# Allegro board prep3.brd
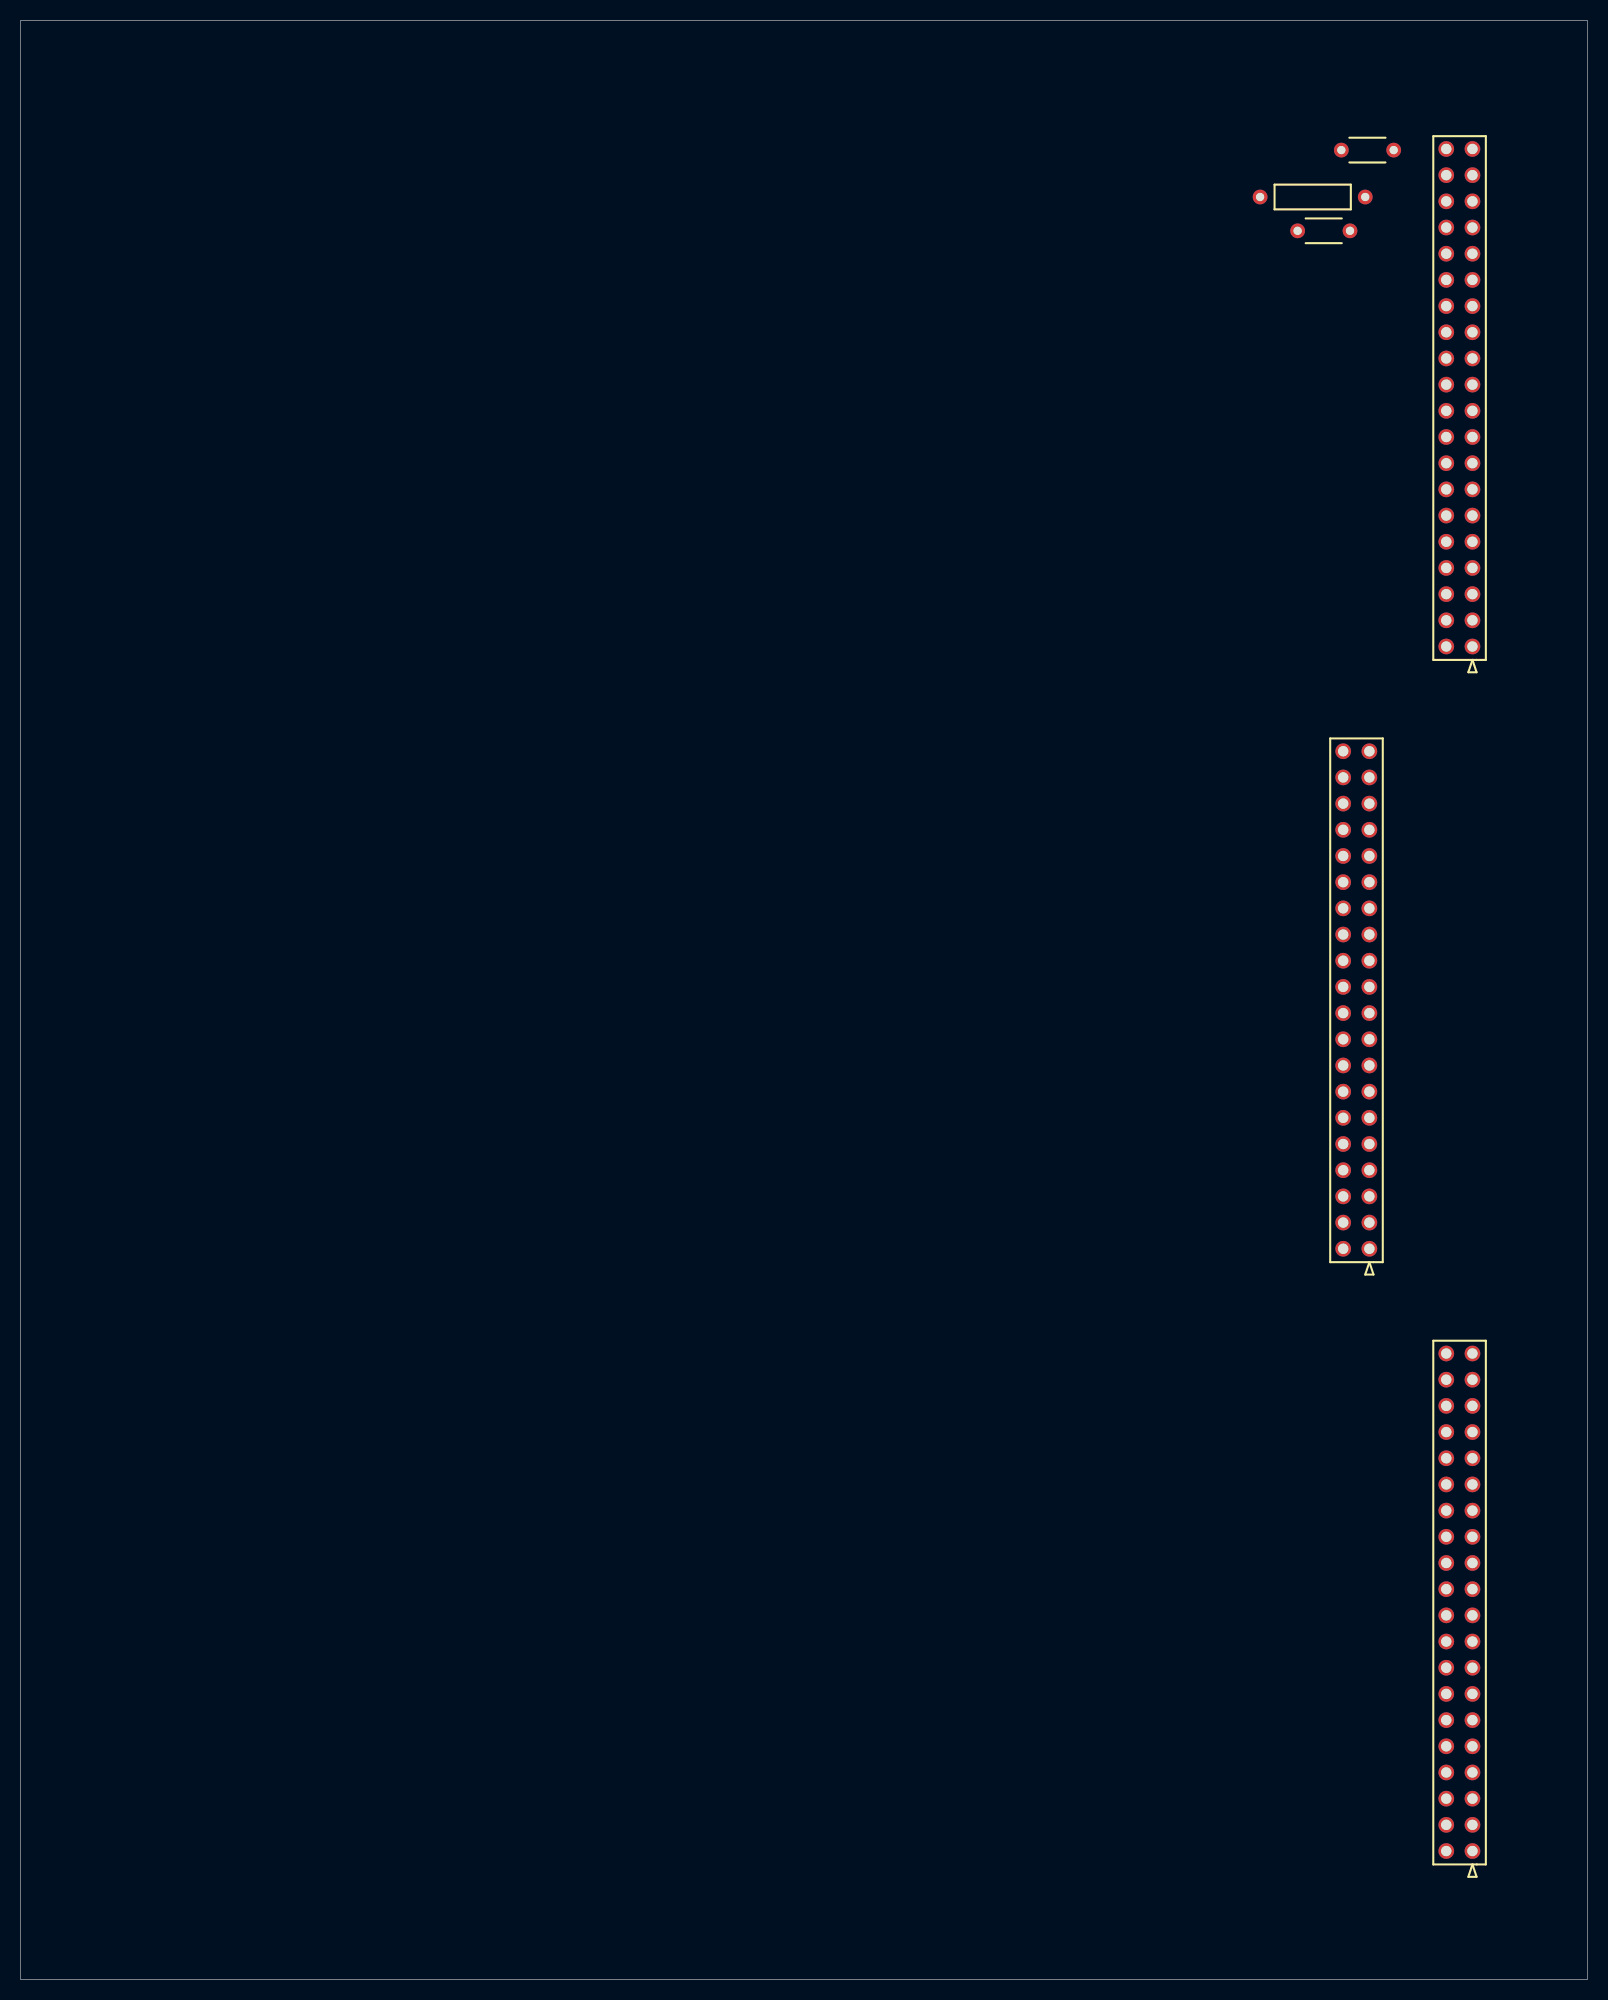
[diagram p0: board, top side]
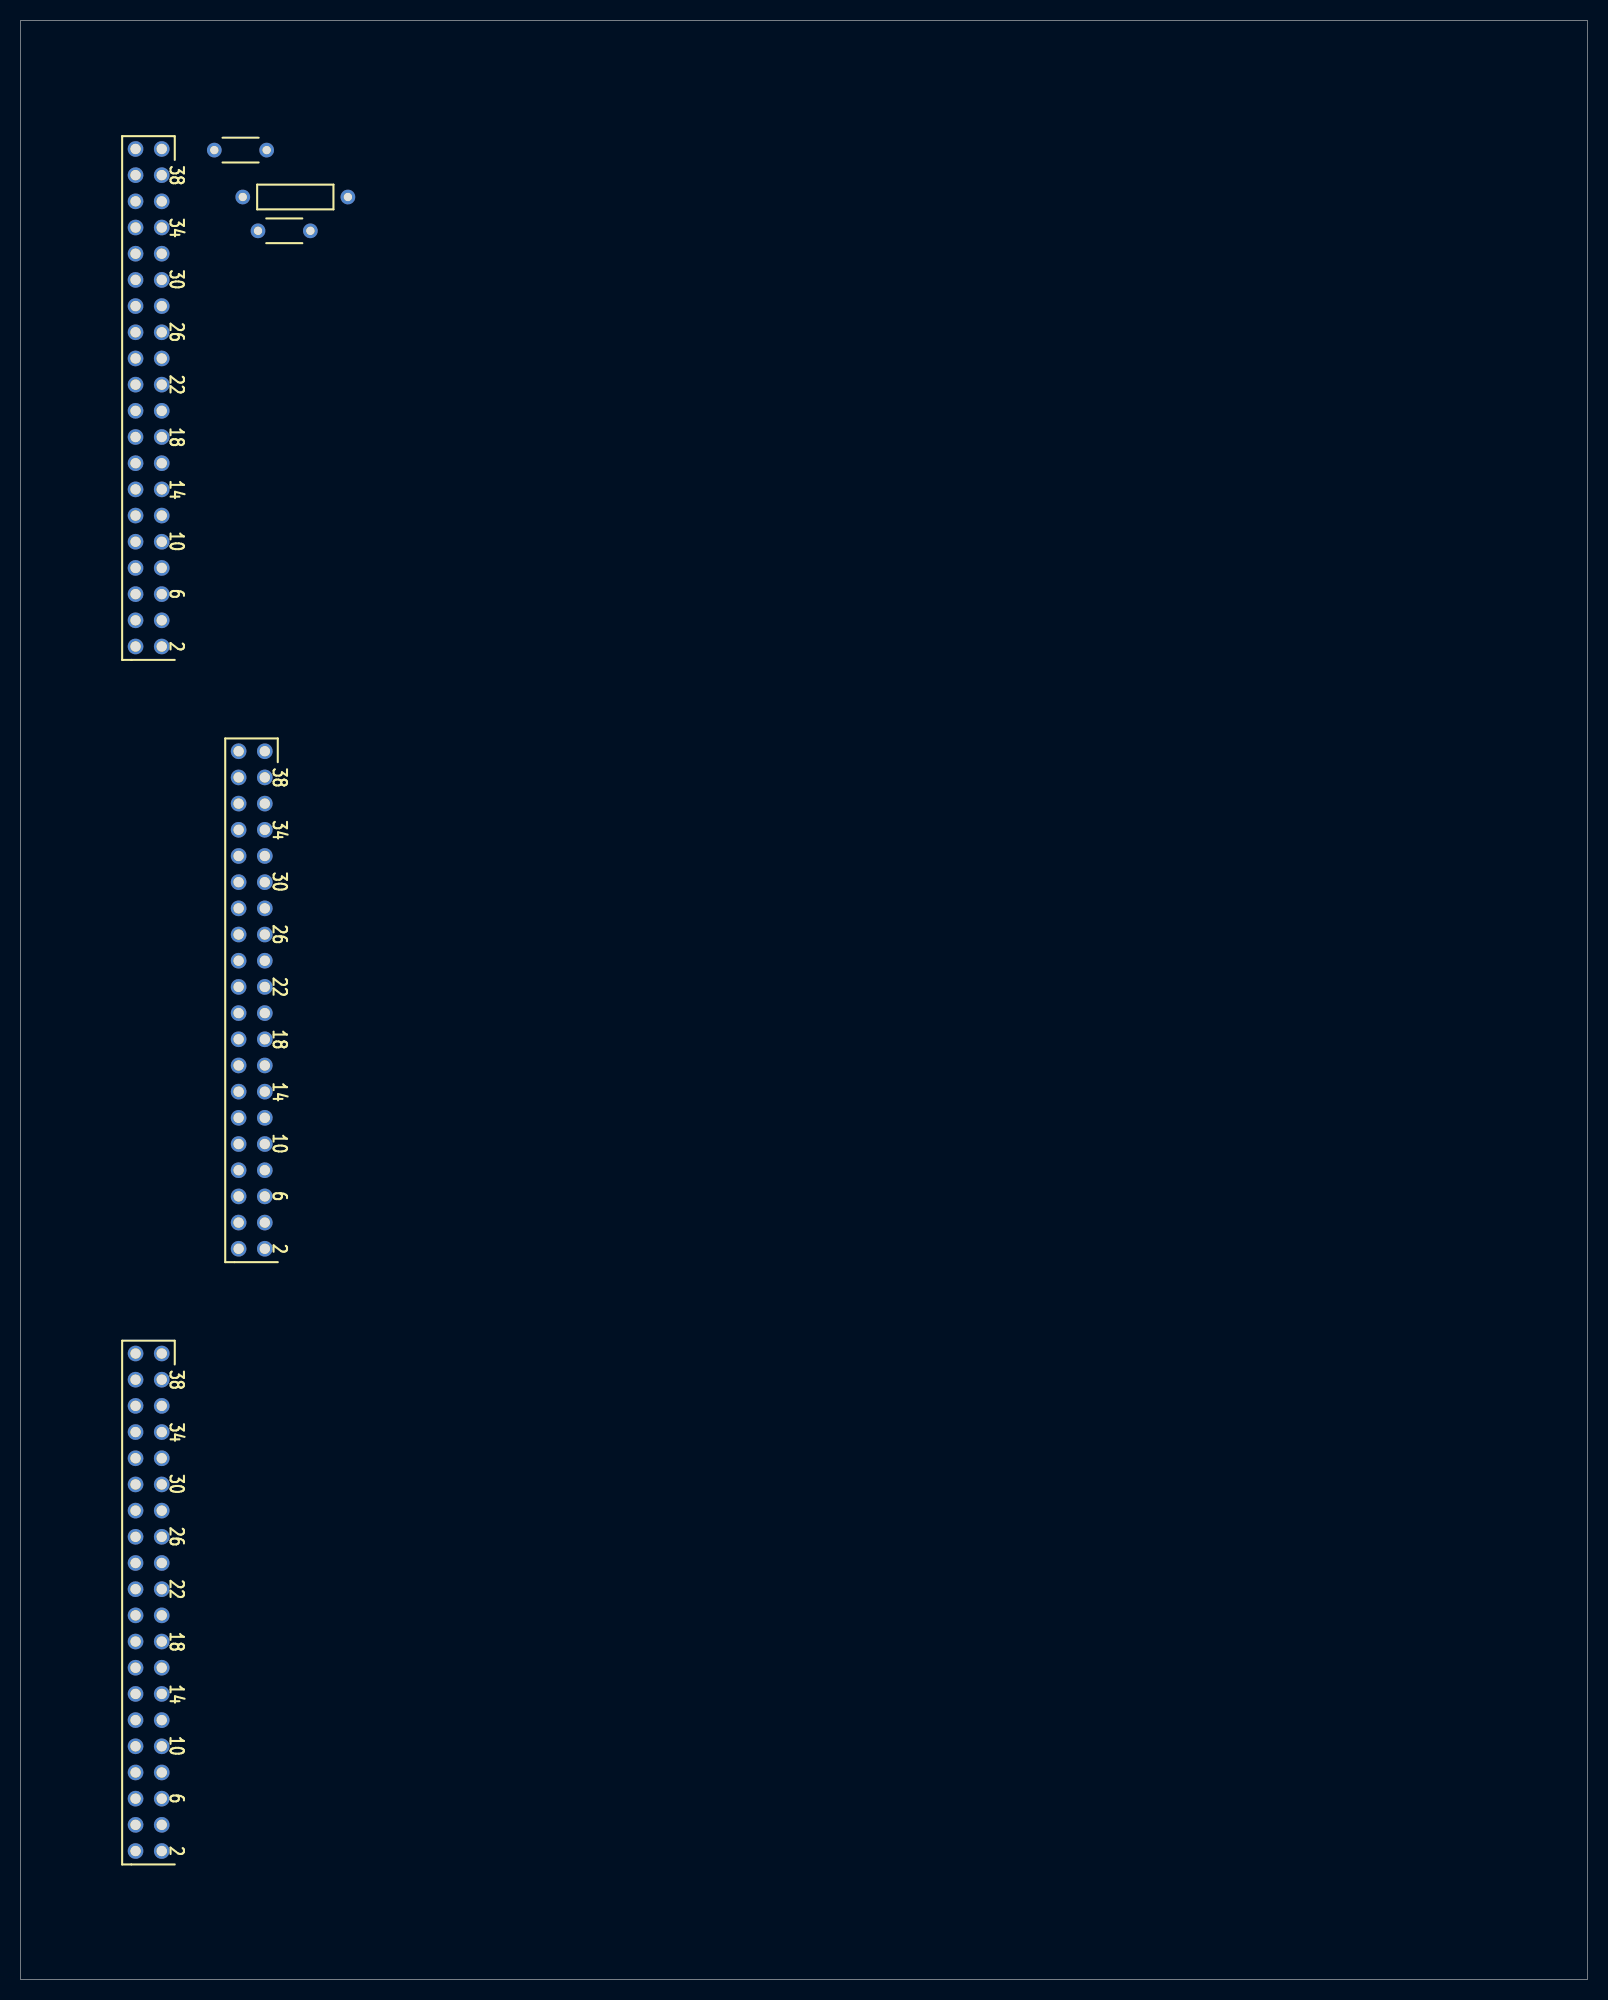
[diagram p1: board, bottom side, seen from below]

Outline 152 x 190 mm; copper layers: TOP, BOTTOM. Coordinates in mm from the lower left corner of the outline.
Outline path: 0,190 152,190 152,0 0,0 0,190

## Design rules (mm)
constraint set DEFAULT: min track width 0.15, pair gap 0.15

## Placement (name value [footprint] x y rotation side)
J1  -  [CONHE13D2X20M]  140.85 129.29 0 top
J2  -  [CONHE13D2X20M]  130.85 70.87 0 top
J3  -  [CONHE13D2X20M]  140.85 12.45 0 top
NOREF  -  []  0 0 0 top
NOREF#2  -  []  0 0 90 top
R1  100  [R50]  133.21 177.44 180 top
R2  100  [R100]  130.45 172.89 180 top
R3  100  [R50]  128.97 169.61 180 top

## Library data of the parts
J1-J3 = CON40P: part number: CON40P-HE13D
R1 R3 = RGEN: part number: RGEN-100,C125MW5%
R2 = RGEN: part number: RGEN-100,M500MW5%

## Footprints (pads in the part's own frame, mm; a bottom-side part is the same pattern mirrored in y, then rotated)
CONHE13D2X20M
  round 1.52 hole 1: 1(0,0) 2(-2.54,0) 3(0,2.54) 4(-2.54,2.54) 5(0,5.08) 6(-2.54,5.08) 7(0,7.62) 8(-2.54,7.62) 9(0,10.16) 10(-2.54,10.16) 11(0,12.7) 12(-2.54,12.7) 13(0,15.24) 14(-2.54,15.24) 15(0,17.78) 16(-2.54,17.78) 17(0,20.32) 18(-2.54,20.32) 19(0,22.86) 20(-2.54,22.86) 21(0,25.4) 22(-2.54,25.4) 23(0,27.94) 24(-2.54,27.94) 25(0,30.48) 26(-2.54,30.48) 27(0,33.02) 28(-2.54,33.02) 29(0,35.56) 30(-2.54,35.56) 31(0,38.1) 32(-2.54,38.1) 33(0,40.64) 34(-2.54,40.64) 35(0,43.18) 36(-2.54,43.18) 37(0,45.72) 38(-2.54,45.72) 39(0,48.26) 40(-2.54,48.26)
R50
  round 1.43 hole 0.8: 1(0,0) 2(5.08,0)
R100
  round 1.43 hole 0.8: 1(0,0) 2(10.2,0)

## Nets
GND: J1.1 J1.3 J1.5 J1.7 J1.9 J1.11 J1.13 J1.15 J1.17 J1.19 J1.21 J1.23 J1.25 J1.27 J1.29 J1.31 J1.33 J1.35 J1.37 J1.39 J2.1 J2.3 J2.5 J2.7 J2.9 J2.11 J2.13 J2.15 J2.17 J2.19 J2.21 J2.23 J2.25 J2.27 J2.29 J2.31 J2.33 J2.35 J2.37 J2.39 J3.1 J3.3 J3.5 J3.7 J3.9 J3.11 J3.13 J3.15 J3.17 J3.19 J3.21 J3.23 J3.25 J3.27 J3.29 J3.31 J3.33 J3.35 J3.37 J3.39
UNNAMED_1_CON40P_I1_A: J1.10(A<9>)
UNNAMED_1_CON40P_I1_A_1: J1.8
UNNAMED_1_CON40P_I1_A_2: J1.6
UNNAMED_1_CON40P_I1_A_3: J1.4
UNNAMED_1_CON40P_I1_A_4: J1.40 R1.1
UNNAMED_1_CON40P_I1_A_5: J1.38 R2.1
UNNAMED_1_CON40P_I1_A_6: J1.36 R3.1
UNNAMED_1_CON40P_I1_A_7: J1.34
UNNAMED_1_CON40P_I1_A_8: J1.32
UNNAMED_1_CON40P_I1_A_9: J1.30
UNNAMED_1_CON40P_I1_A_10: J1.28
UNNAMED_1_CON40P_I1_A_11: J1.26
UNNAMED_1_CON40P_I1_A_12: J1.24
UNNAMED_1_CON40P_I1_A_13: J1.22
UNNAMED_1_CON40P_I1_A_14: J1.2
UNNAMED_1_CON40P_I1_A_15: J1.20
UNNAMED_1_CON40P_I1_A_16: J1.18
UNNAMED_1_CON40P_I1_A_17: J1.16
UNNAMED_1_CON40P_I1_A_18: J1.14
UNNAMED_1_CON40P_I1_A_19: J1.12
UNNAMED_1_CON40P_I2_A: J2.28
UNNAMED_1_CON40P_I2_A_1: J2.30
UNNAMED_1_CON40P_I2_A_2: J2.38
UNNAMED_1_CON40P_I2_A_3: J2.32
UNNAMED_1_CON40P_I2_A_4: J2.34
UNNAMED_1_CON40P_I2_A_5: J2.36
UNNAMED_1_CON40P_I2_A_6: J2.40
UNNAMED_1_CON40P_I2_A_7: J2.6
UNNAMED_1_CON40P_I2_A_8: J2.8
UNNAMED_1_CON40P_I2_A_9: J2.4
UNNAMED_1_CON40P_I2_A_10: J2.2
UNNAMED_1_CON40P_I2_A_11: J2.10(A<9>)
UNNAMED_1_CON40P_I2_A_12: J2.12
UNNAMED_1_CON40P_I2_A_13: J2.14
UNNAMED_1_CON40P_I2_A_14: J2.16
UNNAMED_1_CON40P_I2_A_15: J2.18
UNNAMED_1_CON40P_I2_A_16: J2.20
UNNAMED_1_CON40P_I2_A_17: J2.22
UNNAMED_1_CON40P_I2_A_18: J2.24
UNNAMED_1_CON40P_I2_A_19: J2.26
UNNAMED_1_CON40P_I3_A: J3.28
UNNAMED_1_CON40P_I3_A_1: J3.30
UNNAMED_1_CON40P_I3_A_2: J3.38
UNNAMED_1_CON40P_I3_A_3: J3.32
UNNAMED_1_CON40P_I3_A_4: J3.34
UNNAMED_1_CON40P_I3_A_5: J3.36
UNNAMED_1_CON40P_I3_A_6: J3.40
UNNAMED_1_CON40P_I3_A_7: J3.6
UNNAMED_1_CON40P_I3_A_8: J3.8
UNNAMED_1_CON40P_I3_A_9: J3.4
UNNAMED_1_CON40P_I3_A_10: J3.2
UNNAMED_1_CON40P_I3_A_11: J3.10(A<9>)
UNNAMED_1_CON40P_I3_A_12: J3.12
UNNAMED_1_CON40P_I3_A_13: J3.14
UNNAMED_1_CON40P_I3_A_14: J3.16
UNNAMED_1_CON40P_I3_A_15: J3.18
UNNAMED_1_CON40P_I3_A_16: J3.20
UNNAMED_1_CON40P_I3_A_17: J3.22
UNNAMED_1_CON40P_I3_A_18: J3.24
UNNAMED_1_CON40P_I3_A_19: J3.26
UNNAMED_1_POT_I5_B: R1.2(B<0>)
UNNAMED_1_POT_I7_B: R2.2(B<0>)
UNNAMED_1_POT_I26_B: R3.2(B<0>)
